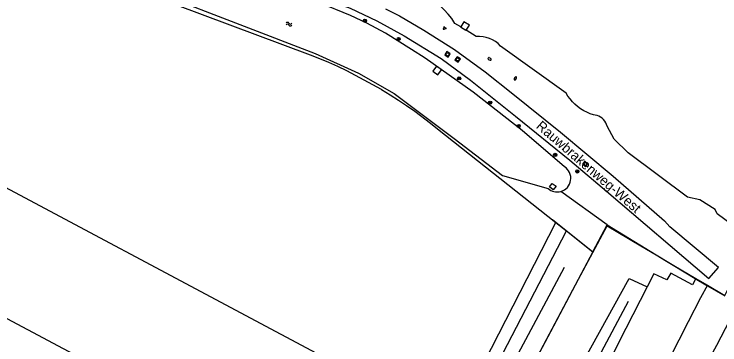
# Model space of a CAD drawing. Extents: x 136000 to 138005, y 398500 to 400500.
# Drawn here: x 136830.4 to 137009.8, y 399263.7 to 399347.7 of the extents above; entities that cross this region are included whole.
import ezdxf

# ---------------------------------------------------------------- set-up
doc = ezdxf.new("R2010")
doc.units = 0
for name, color, linetype in [('gg-afsc-hekwerk', 7, 'Continuous'), ('gg-anno-openbare ruimte label', 7, 'Continuous'), ('gg-aspt-spoorlijn', 7, 'Continuous'), ('gg-bbg-hoofdgebouw', 7, 'Continuous'), ('gg-knt-verharding', 7, 'Continuous'), ('gg-kntw-bovenkant insteek waterloop', 7, 'Continuous'), ('gg-kwrk-uitstroombak niveau min 01', 7, 'Continuous'), ('gt-grn-groengrens', 7, 'Continuous'), ('gt-symb-boom', 7, 'Continuous'), ('gt-symb-brandkraan', 7, 'Continuous'), ('gt-symb-groenvak', 7, 'Continuous'), ('gt-symb-rioolschacht', 7, 'Continuous'), ('gt-symb-watersymbool', 7, 'Continuous'), ('gx-grn-maaiveld', 7, 'Continuous')]:
    doc.layers.add(name, color=color, linetype=linetype)

# ---------------------------------------------------------------- blocks, each defined once
blk = doc.blocks.new('gt0-BOOM')
at = {"layer": 'gt-symb-boom'}
for radius in [0.4, 0.2]:
    blk.add_circle((0, 0), radius, dxfattribs=at)
blk = doc.blocks.new('gt0-BR')
at = {"layer": 'gt-symb-brandkraan'}
for centre, radius, start, end in [((-0.24, 0), 0.206, 107.5669, 252.4331), ((0.6, -2.66), 3, 106.892, 107.5669), ((0, -0.69), 0.938, 73.108, 106.892), ((-0.6, -2.66), 3, 72.4331, 73.108), ((0.24, 0), 0.206, 287.567, 72.4331), ((0.6, 2.66), 3, 252.4331, 253.108), ((0, 0.69), 0.938, 253.108, 286.8921), ((-0.6, 2.66), 3, 286.8921, 287.567)]:
    blk.add_arc(centre, radius, start, end, dxfattribs=at)
blk = doc.blocks.new('gt0-RS')
at = {"layer": 'gt-symb-rioolschacht'}
blk.add_lwpolyline([(-0.5, -0.5), (0.5, -0.5), (0.5, 0.5), (-0.5, 0.5)], close=True, dxfattribs=at)
blk.add_circle((0, 0), 0.375, dxfattribs=at)
blk = doc.blocks.new('gt0-GRVAK')
at = {"layer": 'gt-symb-groenvak'}
for p, q in [((-0.11, 0.19), (-0.23, 0.24)), ((-0.18, 0.15), (0.09, 0.15)), ((-0.09, 0.21), (-0.16, 0.32)), ((-0.05, 0.21), (-0.05, 0.39)), ((0, 0.21), (0.06, 0.32)), ((0.01, 0.19), (0.13, 0.24)), ((0.26, -0.05), (0.2, 0.06)), ((0.3, -0.05), (0.3, 0.13)), ((0.35, -0.05), (0.41, 0.06)), ((-0.24, -0.23), (-0.36, -0.18)), ((-0.32, -0.26), (-0.05, -0.26)), ((-0.23, -0.21), (-0.29, -0.1)), ((-0.18, -0.2), (-0.18, -0.02)), ((-0.14, -0.21), (-0.07, -0.1)), ((-0.12, -0.23), (0, -0.18)), ((0.24, -0.07), (0.12, -0.02)), ((0.17, -0.11), (0.44, -0.11)), ((0.37, -0.07), (0.49, -0.02))]:
    blk.add_line(p, q, dxfattribs=at)
blk = doc.blocks.new('gt0-WA')
at = {"layer": 'gt-symb-watersymbool'}
for centre, start, end in [((-0.32, 0.02), 28.0725, 151.9275), ((0.43, 0.42), 208.0725, 331.9275), ((-0.32, -0.43), 28.0725, 151.9275), ((0.43, -0.03), 208.0725, 331.9275)]:
    blk.add_arc(centre, 0.425, start, end, dxfattribs=at)

msp = doc.modelspace()

# ---------------------------------------------------------------- linework, layer by layer
at = {"layer": 'gg-afsc-hekwerk'}
msp.add_line((136967.21, 399295.61), (136977.51, 399287.4), dxfattribs=at)
for points in [[(136923.78, 399328.57), (136919.38, 399330.99), (136917.16, 399332.17), (136914.92, 399333.32), (136912.65, 399334.41), (136910.36, 399335.47), (136908.12, 399336.37), (136905.76, 399337.27), (136809.23, 399373.39), (136734.6, 399401.33), (136696.62, 399421.55)], [(136939.13, 399244.62), (136776.9, 399330.95), (136783.9, 399344.36), (136786.28, 399345.36), (136802.46, 399375.92)], [(136923.78, 399328.57), (136919.38, 399330.99), (136917.16, 399332.17), (136914.92, 399333.32), (136912.65, 399334.41), (136910.36, 399335.47), (136908.12, 399336.37), (136905.76, 399337.27), (136809.23, 399373.39), (136802.46, 399375.92)], [(136923.78, 399328.57), (136925.95, 399327.27), (136928.06, 399325.92), (136930.14, 399324.54), (136932.2, 399323.09), (136936.2, 399320.05), (136938.04, 399318.59), (136968.1, 399294.81)], [(136923.78, 399328.57), (136925.95, 399327.27), (136928.06, 399325.92), (136930.14, 399324.54), (136932.2, 399323.09), (136936.2, 399320.05), (136938.04, 399318.59), (136968.1, 399294.81)], [(136854.56, 399056.13), (136859.43, 399065.25), (136864.05, 399073.93), (136868.71, 399082.72), (136872.25, 399089.38), (136884.31, 399111.94), (136897.12, 399136.05), (136966.79, 399267.12), (136973.84, 399280.45), (136981.11, 399294)], [(136981.11, 399294), (136989.68, 399288.93), (136994.01, 399286.32), (136998.34, 399283.72), (137003.54, 399280.61), (137006.63, 399278.76), (137011.01, 399276.17)]]:
    msp.add_lwpolyline(points, dxfattribs=at)
at = {"layer": 'gg-aspt-spoorlijn'}
for points in [[(136945.42, 399237.07), (136970.32, 399283.5)], [(136830.88, 398928.69), (136835.9, 398940.34), (136838.69, 398947.02), (136840.02, 398950.37), (136842.36, 398956.97), (136845.42, 398967.63), (136856.44, 399016.13), (136857.83, 399022.1), (136859.77, 399029.32), (136861.05, 399033.42), (136862.9, 399038.89), (136864.93, 399044.08), (136867.26, 399049.51), (136869.91, 399055.2), (136872.2, 399059.56), (136908.87, 399128.35), (136924.25, 399157.44), (136955.17, 399215.38), (136971.48, 399246.54), (136986.53, 399274.81)]]:
    msp.add_lwpolyline(points, dxfattribs=at)
at = {"layer": 'gg-bbg-hoofdgebouw'}
msp.add_lwpolyline([(136770.27, 399172.35), (136766.48, 399165.23), (136795.65, 399149.72), (136799.41, 399156.83), (136870.89, 399118.81), (136924.35, 399219.4), (136752.33, 399310.92), (136698.79, 399210.34), (136770.27, 399172.35)], dxfattribs=at)
at = {"layer": 'gg-knt-verharding'}
for points in [[(136904.41, 399353.51), (136915.81, 399349.23), (136922.55, 399346.05), (136929.54, 399342.24), (136938.97, 399336.5), (136946.42, 399330.99), (136957.83, 399321.81), (136971.6, 399310.66), (136980.98, 399302.81)], [(136924.75, 399349.09), (136928.32, 399347.26), (136934.52, 399343.67), (136942.34, 399338.74), (136950.1, 399333.08), (136957.11, 399327.52), (136969.23, 399317.74), (136982.64, 399306.56), (136995.68, 399295.21)], [(136980.98, 399302.81), (137006.99, 399280.61), (137009.46, 399283.35), (136997.07, 399293.73), (136995.68, 399295.21)]]:
    msp.add_lwpolyline(points, dxfattribs=at)
at = {"layer": 'gg-kntw-bovenkant insteek waterloop'}
for p, q in [((136943.9, 399344.47), (136942.44, 399345.37)), ((136947.85, 399342.02), (136945.26, 399343.62)), ((136970.69, 399327.69), (136954.04, 399339.63))]:
    msp.add_line(p, q, dxfattribs=at)
for points in [[(136804.52, 399376.37), (136807.15, 399375.26), (136808.67, 399374.16), (136811.09, 399373.19), (136813.67, 399372.83), (136819.07, 399371.47), (136830.99, 399367.44), (136834.7, 399366.25), (136838.07, 399365.96), (136841.31, 399364.93), (136844.77, 399363.24), (136848.37, 399360.36), (136906.9, 399337.77), (136917.9, 399332.73), (136927.01, 399327.61), (136942.27, 399316.15), (136954.52, 399306.79), (136966.11, 399303.46)], [(136970.27, 399308.97), (136959.55, 399318.15), (136947.1, 399327.87), (136934.87, 399336.58), (136931.37, 399338.77), (136924.75, 399342.92), (136920.04, 399345.46), (136915.85, 399347.42), (136908.02, 399350.61), (136878.82, 399360.81), (136855.03, 399369.16), (136844.26, 399372.89)], [(136942.44, 399345.37), (136941.61, 399346.58), (136940.69, 399347.74), (136939.69, 399348.84), (136938.62, 399349.89), (136937.48, 399350.86), (136936.28, 399351.75), (136935.03, 399352.57), (136933.73, 399353.29), (136932.39, 399353.93), (136931.03, 399354.47)], [(136977.67, 399322.18), (136976.82, 399322.45), (136975.98, 399322.8), (136975.16, 399323.21), (136974.38, 399323.69), (136973.63, 399324.23), (136972.93, 399324.84), (136972.28, 399325.49), (136971.69, 399326.19), (136971.16, 399326.92), (136970.69, 399327.69)], [(136981.12, 399319.31), (136980.98, 399319.74), (136980.77, 399320.16), (136980.51, 399320.57), (136980.2, 399320.94), (136979.84, 399321.28), (136979.45, 399321.57), (136979.02, 399321.81), (136978.57, 399321.99), (136978.12, 399322.11), (136977.67, 399322.18)], [(137016.54, 399291.48), (137009.13, 399296.98), (137008.58, 399298.08), (137004.72, 399300.58), (137001.58, 399301.22), (136986.43, 399312.47), (136982.88, 399315.95), (136981.12, 399319.31)]]:
    msp.add_lwpolyline(points, dxfattribs=at)
for centre, radius, start, end in [((136948.45, 399334.37), 7.68, 43.2384, 94.4573), ((136968.42, 399306.04), 3.47, 284.9996, 57.6014), ((136968.42, 399306.04), 3.47, 228.1776, 284.9972)]:
    msp.add_arc(centre, radius, start, end, dxfattribs=at)
at = {"layer": 'gg-kwrk-uitstroombak niveau min 01'}
for points in [[(136945.26, 399343.62), (136946.1, 399344.89), (136944.73, 399345.76), (136943.9, 399344.47)], [(136945.26, 399343.62), (136945.2, 399343.53), (136943.87, 399344.42), (136943.9, 399344.47)], [(136937.73, 399334.51), (136936.81, 399333.21), (136938.12, 399332.29), (136939.06, 399333.59), (136937.73, 399334.51)], [(136967.43, 399303.09), (136966.45, 399303.83), (136967.17, 399304.75), (136968.16, 399304.01), (136967.43, 399303.09)]]:
    msp.add_lwpolyline(points, dxfattribs=at)
at = {"layer": 'gt-grn-groengrens'}
msp.add_line((136981.15, 399294.2), (136969.32, 399302.7), dxfattribs=at)
at = {"layer": 'gx-grn-maaiveld'}
for p, q in [((136941.59, 399243.32), (136968.1, 399294.81)), ((136968.1, 399294.81), (136970.8, 399292.68)), ((136944.34, 399241.87), (136970.8, 399292.68)), ((136970.8, 399292.68), (136977.51, 399287.4)), ((136977.51, 399287.4), (136981.15, 399294.2)), ((136977.51, 399287.4), (136951.32, 399238.26)), ((137003.68, 399280.59), (137006.61, 399278.86))]:
    msp.add_line(p, q, dxfattribs=at)
for points in [[(136981.15, 399294.2), (136996.18, 399285.01), (137003.68, 399280.59)], [(137003.68, 399280.59), (137002.86, 399278.99), (136997.3, 399281.93), (136996.33, 399280.29), (136992.96, 399281.78), (136991.28, 399278.49)], [(137006.61, 399278.86), (137011.05, 399276.25), (137014.1, 399282.39)], [(136874.42, 399058.58), (136864.9, 399034.01), (136849.64, 398972.69), (136846.05, 398959.45), (136875.88, 399014.34), (136889.18, 399039.92), (136917.86, 399093.92), (136933.1, 399123.35), (136946.94, 399149.57), (136963.28, 399180.19), (136980.05, 399210.93), (137008.98, 399263.69), (137017.74, 399280.41)], [(136894.92, 399109.27), (136906.91, 399131.32), (136924.51, 399164.43), (136945.92, 399204.71), (136971.61, 399253.32), (136986.71, 399280.6), (136991.28, 399278.49)], [(137006.61, 399278.86), (137004.83, 399275.72), (137001.68, 399269.61), (136994.57, 399255.6), (136995.17, 399255.33), (136988.35, 399242.11), (136983.96, 399233.71), (136989.29, 399230.92), (136981.01, 399214.97), (136973.86, 399201.35), (136968.55, 399204.18), (136968, 399203.05), (136957.42, 399208.36), (136958.03, 399209.54), (136956.66, 399210.42)], [(136991.28, 399278.49), (136985.84, 399267.86), (136980.29, 399256.82), (136980.44, 399256.03), (136973.34, 399242.08), (136960.57, 399217.73), (136956.66, 399210.42)]]:
    msp.add_lwpolyline(points, dxfattribs=at)

# ---------------------------------------------------------------- block references
at = {"layer": 'gt-symb-boom'}
for p in [(136919.55, 399346.04), (136928.12, 399341.4), (136943.52, 399331.42), (136951.39, 399325.26), (136958.64, 399319.34), (136967.93, 399311.98), (136973.54, 399307.78)]:
    msp.add_blockref('gt0-BOOM', p, dxfattribs=at)
at = {"layer": 'gt-symb-brandkraan'}
for p, rotation in [((136951.25, 399336.35), -30.59043540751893), ((136957.79, 399331.39), -120.38423729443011)]:
    msp.add_blockref('gt0-BR', p, dxfattribs=dict(at, rotation=rotation))
at = {"layer": 'gt-symb-groenvak'}
msp.add_blockref('gt0-GRVAK', (136939.79, 399344.17), dxfattribs=at)
at = {"layer": 'gt-symb-rioolschacht'}
for p, rotation in [((136940.56, 399337.51), -32.26035320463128), ((136943.13, 399336.23), -33.70595653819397), ((136975.54, 399309.68), -40.94326213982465)]:
    msp.add_blockref('gt0-RS', p, dxfattribs=dict(at, rotation=rotation))
at = {"layer": 'gt-symb-watersymbool'}
msp.add_blockref('gt0-WA', (136900.19, 399345.19), dxfattribs=at)

# ---------------------------------------------------------------- texts
at = {"layer": 'gg-anno-openbare ruimte label'}
msp.add_text('Rauwbrakenweg-West', height=2.5, rotation=319.3, dxfattribs=at).set_placement((136962.88, 399318.97))

doc.saveas('drawing.dxf')
